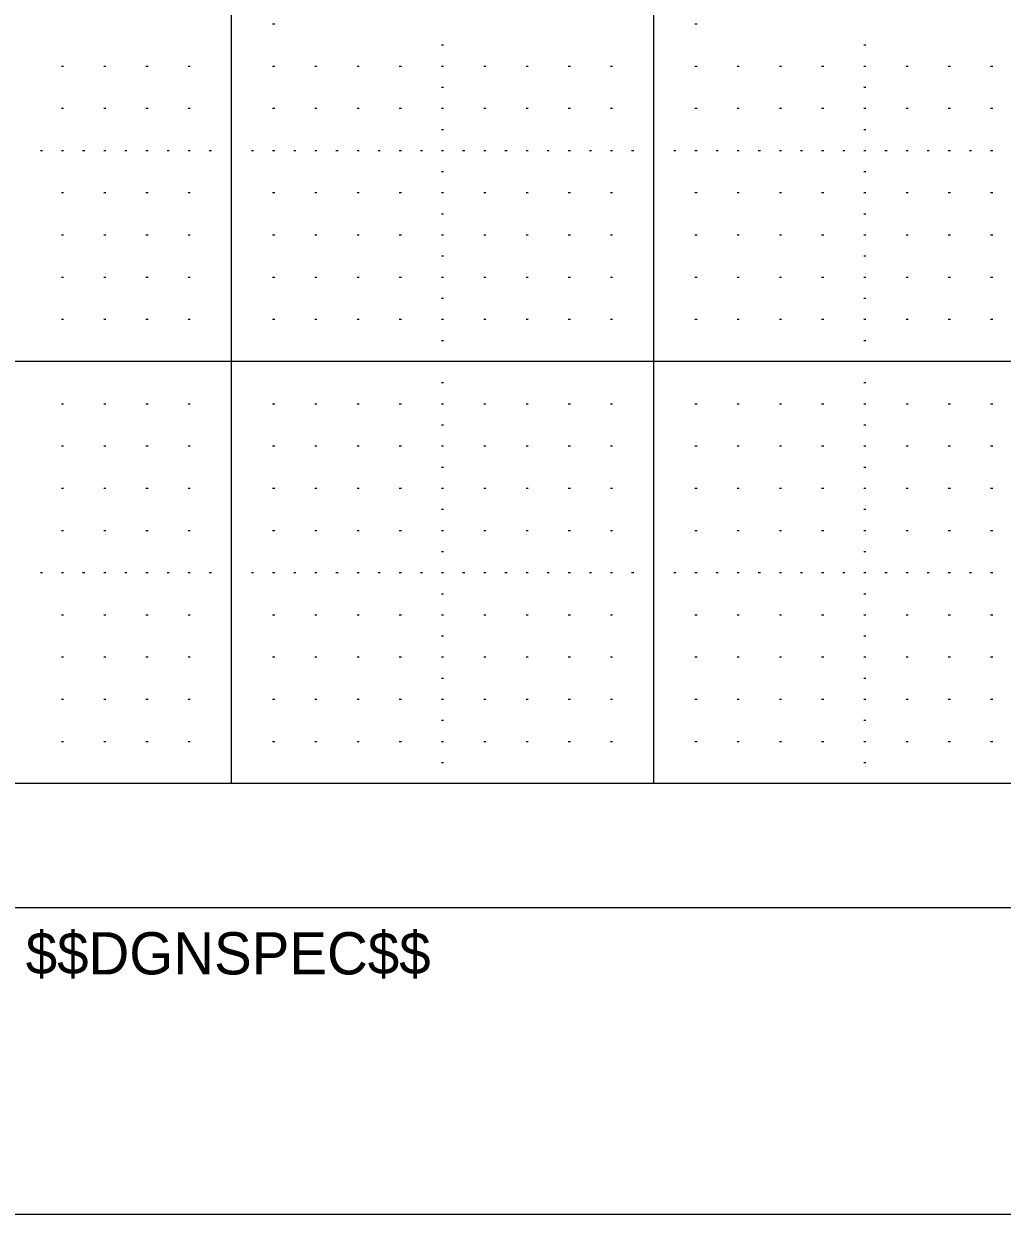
# Model space of a CAD drawing. Extents: x -1.3 to 32.7, y -0.7 to 21.3.
# Drawn here: x 19.601 to 21.917, y -0.727 to 2.093 of the extents above; entities that cross this region are included whole.
import ezdxf

# ---------------------------------------------------------------- set-up
doc = ezdxf.new("R2010")
doc.units = 0
for name, color, linetype in [('Level 1', 7, 'Continuous'), ('Level 4', 7, 'Continuous'), ('Level 48', 7, 'Continuous'), ('Level 5', 7, 'Continuous'), ('Level 63', 7, 'Continuous'), ('R_Border_Dark', 7, 'Continuous')]:
    doc.layers.add(name, color=color, linetype=linetype)

msp = doc.modelspace()

# ---------------------------------------------------------------- linework, layer by layer
at = {"layer": 'Level 1'}
msp.add_line((31.9643, -0.001), (0.3463, -0.001), dxfattribs=at)
at = {"layer": 'Level 4'}
msp.add_line((31.9643, 0.293), (0.3463, 0.293), dxfattribs=at)
at = {"layer": 'Level 5'}
for p, q in [((20.1898, 2.093), (20.1948, 2.093)), ((21.1898, 2.093), (21.1948, 2.093)), ((20.5898, 2.043), (20.5948, 2.043)), ((21.5898, 2.043), (21.5948, 2.043)), ((19.6898, 1.993), (19.6948, 1.993)), ((19.7898, 1.993), (19.7948, 1.993)), ((19.8898, 1.993), (19.8948, 1.993)), ((19.9898, 1.993), (19.9948, 1.993)), ((20.1898, 1.993), (20.1948, 1.993)), ((20.2898, 1.993), (20.2948, 1.993)), ((20.3898, 1.993), (20.3948, 1.993)), ((20.4898, 1.993), (20.4948, 1.993)), ((20.5898, 1.993), (20.5948, 1.993)), ((20.6898, 1.993), (20.6948, 1.993)), ((20.7898, 1.993), (20.7948, 1.993)), ((20.8898, 1.993), (20.8948, 1.993)), ((20.9898, 1.993), (20.9948, 1.993)), ((21.1898, 1.993), (21.1948, 1.993)), ((21.2898, 1.993), (21.2948, 1.993)), ((21.3898, 1.993), (21.3948, 1.993)), ((21.4898, 1.993), (21.4948, 1.993)), ((21.5898, 1.993), (21.5948, 1.993)), ((21.6898, 1.993), (21.6948, 1.993)), ((21.7898, 1.993), (21.7948, 1.993)), ((21.8898, 1.993), (21.8948, 1.993)), ((20.5898, 1.943), (20.5948, 1.943)), ((21.5898, 1.943), (21.5948, 1.943)), ((19.6898, 1.893), (19.6948, 1.893)), ((19.7898, 1.893), (19.7948, 1.893)), ((19.8898, 1.893), (19.8948, 1.893)), ((19.9898, 1.893), (19.9948, 1.893)), ((20.1898, 1.893), (20.1948, 1.893)), ((20.2898, 1.893), (20.2948, 1.893)), ((20.3898, 1.893), (20.3948, 1.893)), ((20.4898, 1.893), (20.4948, 1.893)), ((20.5898, 1.893), (20.5948, 1.893)), ((20.6898, 1.893), (20.6948, 1.893)), ((20.7898, 1.893), (20.7948, 1.893)), ((20.8898, 1.893), (20.8948, 1.893)), ((20.9898, 1.893), (20.9948, 1.893)), ((21.1898, 1.893), (21.1948, 1.893)), ((21.2898, 1.893), (21.2948, 1.893)), ((21.3898, 1.893), (21.3948, 1.893)), ((21.4898, 1.893), (21.4948, 1.893)), ((21.5898, 1.893), (21.5948, 1.893)), ((21.6898, 1.893), (21.6948, 1.893)), ((21.7898, 1.893), (21.7948, 1.893)), ((21.8898, 1.893), (21.8948, 1.893)), ((20.5898, 1.843), (20.5948, 1.843)), ((21.5898, 1.843), (21.5948, 1.843)), ((19.6398, 1.793), (19.6448, 1.793)), ((19.6898, 1.793), (19.6948, 1.793)), ((19.7398, 1.793), (19.7448, 1.793)), ((19.7898, 1.793), (19.7948, 1.793)), ((19.8398, 1.793), (19.8448, 1.793)), ((19.8898, 1.793), (19.8948, 1.793)), ((19.9398, 1.793), (19.9448, 1.793)), ((19.9898, 1.793), (19.9948, 1.793)), ((20.0398, 1.793), (20.0448, 1.793)), ((20.1398, 1.793), (20.1448, 1.793)), ((20.1898, 1.793), (20.1948, 1.793)), ((20.2398, 1.793), (20.2448, 1.793)), ((20.2898, 1.793), (20.2948, 1.793)), ((20.3398, 1.793), (20.3448, 1.793)), ((20.3898, 1.793), (20.3948, 1.793)), ((20.4398, 1.793), (20.4448, 1.793)), ((20.4898, 1.793), (20.4948, 1.793)), ((20.5398, 1.793), (20.5448, 1.793)), ((20.5898, 1.793), (20.5948, 1.793)), ((20.6398, 1.793), (20.6448, 1.793)), ((20.6898, 1.793), (20.6948, 1.793)), ((20.7398, 1.793), (20.7448, 1.793)), ((20.7898, 1.793), (20.7948, 1.793)), ((20.8398, 1.793), (20.8448, 1.793)), ((20.8898, 1.793), (20.8948, 1.793)), ((20.9398, 1.793), (20.9448, 1.793)), ((20.9898, 1.793), (20.9948, 1.793)), ((21.0398, 1.793), (21.0448, 1.793)), ((21.1398, 1.793), (21.1448, 1.793)), ((21.1898, 1.793), (21.1948, 1.793)), ((21.2398, 1.793), (21.2448, 1.793)), ((21.2898, 1.793), (21.2948, 1.793)), ((21.3398, 1.793), (21.3448, 1.793)), ((21.3898, 1.793), (21.3948, 1.793)), ((21.4398, 1.793), (21.4448, 1.793)), ((21.4898, 1.793), (21.4948, 1.793)), ((21.5398, 1.793), (21.5448, 1.793)), ((21.5898, 1.793), (21.5948, 1.793)), ((21.6398, 1.793), (21.6448, 1.793)), ((21.6898, 1.793), (21.6948, 1.793)), ((21.7398, 1.793), (21.7448, 1.793)), ((21.7898, 1.793), (21.7948, 1.793)), ((21.8398, 1.793), (21.8448, 1.793)), ((21.8898, 1.793), (21.8948, 1.793)), ((20.5898, 1.743), (20.5948, 1.743)), ((21.5898, 1.743), (21.5948, 1.743)), ((19.6898, 1.693), (19.6948, 1.693)), ((19.7898, 1.693), (19.7948, 1.693)), ((19.8898, 1.693), (19.8948, 1.693)), ((19.9898, 1.693), (19.9948, 1.693)), ((20.1898, 1.693), (20.1948, 1.693)), ((20.2898, 1.693), (20.2948, 1.693)), ((20.3898, 1.693), (20.3948, 1.693)), ((20.4898, 1.693), (20.4948, 1.693)), ((20.5898, 1.693), (20.5948, 1.693)), ((20.6898, 1.693), (20.6948, 1.693)), ((20.7898, 1.693), (20.7948, 1.693)), ((20.8898, 1.693), (20.8948, 1.693)), ((20.9898, 1.693), (20.9948, 1.693)), ((21.1898, 1.693), (21.1948, 1.693)), ((21.2898, 1.693), (21.2948, 1.693)), ((21.3898, 1.693), (21.3948, 1.693)), ((21.4898, 1.693), (21.4948, 1.693)), ((21.5898, 1.693), (21.5948, 1.693)), ((21.6898, 1.693), (21.6948, 1.693)), ((21.7898, 1.693), (21.7948, 1.693)), ((21.8898, 1.693), (21.8948, 1.693)), ((20.5898, 1.643), (20.5948, 1.643)), ((21.5898, 1.643), (21.5948, 1.643)), ((19.6898, 1.593), (19.6948, 1.593)), ((19.7898, 1.593), (19.7948, 1.593)), ((19.8898, 1.593), (19.8948, 1.593)), ((19.9898, 1.593), (19.9948, 1.593)), ((20.1898, 1.593), (20.1948, 1.593)), ((20.2898, 1.593), (20.2948, 1.593)), ((20.3898, 1.593), (20.3948, 1.593)), ((20.4898, 1.593), (20.4948, 1.593)), ((20.5898, 1.593), (20.5948, 1.593)), ((20.6898, 1.593), (20.6948, 1.593)), ((20.7898, 1.593), (20.7948, 1.593)), ((20.8898, 1.593), (20.8948, 1.593)), ((20.9898, 1.593), (20.9948, 1.593)), ((21.1898, 1.593), (21.1948, 1.593)), ((21.2898, 1.593), (21.2948, 1.593)), ((21.3898, 1.593), (21.3948, 1.593)), ((21.4898, 1.593), (21.4948, 1.593)), ((21.5898, 1.593), (21.5948, 1.593)), ((21.6898, 1.593), (21.6948, 1.593)), ((21.7898, 1.593), (21.7948, 1.593)), ((21.8898, 1.593), (21.8948, 1.593)), ((20.5898, 1.543), (20.5948, 1.543)), ((21.5898, 1.543), (21.5948, 1.543)), ((19.6898, 1.493), (19.6948, 1.493)), ((19.7898, 1.493), (19.7948, 1.493)), ((19.8898, 1.493), (19.8948, 1.493)), ((19.9898, 1.493), (19.9948, 1.493)), ((20.1898, 1.493), (20.1948, 1.493)), ((20.2898, 1.493), (20.2948, 1.493)), ((20.3898, 1.493), (20.3948, 1.493)), ((20.4898, 1.493), (20.4948, 1.493)), ((20.5898, 1.493), (20.5948, 1.493)), ((20.6898, 1.493), (20.6948, 1.493)), ((20.7898, 1.493), (20.7948, 1.493)), ((20.8898, 1.493), (20.8948, 1.493)), ((20.9898, 1.493), (20.9948, 1.493)), ((21.1898, 1.493), (21.1948, 1.493)), ((21.2898, 1.493), (21.2948, 1.493)), ((21.3898, 1.493), (21.3948, 1.493)), ((21.4898, 1.493), (21.4948, 1.493)), ((21.5898, 1.493), (21.5948, 1.493)), ((21.6898, 1.493), (21.6948, 1.493)), ((21.7898, 1.493), (21.7948, 1.493)), ((21.8898, 1.493), (21.8948, 1.493)), ((20.5898, 1.443), (20.5948, 1.443)), ((21.5898, 1.443), (21.5948, 1.443)), ((19.6898, 1.393), (19.6948, 1.393)), ((19.7898, 1.393), (19.7948, 1.393)), ((19.8898, 1.393), (19.8948, 1.393)), ((19.9898, 1.393), (19.9948, 1.393)), ((20.1898, 1.393), (20.1948, 1.393)), ((20.2898, 1.393), (20.2948, 1.393)), ((20.3898, 1.393), (20.3948, 1.393)), ((20.4898, 1.393), (20.4948, 1.393)), ((20.5898, 1.393), (20.5948, 1.393)), ((20.6898, 1.393), (20.6948, 1.393)), ((20.7898, 1.393), (20.7948, 1.393)), ((20.8898, 1.393), (20.8948, 1.393)), ((20.9898, 1.393), (20.9948, 1.393)), ((21.1898, 1.393), (21.1948, 1.393)), ((21.2898, 1.393), (21.2948, 1.393)), ((21.3898, 1.393), (21.3948, 1.393)), ((21.4898, 1.393), (21.4948, 1.393)), ((21.5898, 1.393), (21.5948, 1.393)), ((21.6898, 1.393), (21.6948, 1.393)), ((21.7898, 1.393), (21.7948, 1.393)), ((21.8898, 1.393), (21.8948, 1.393)), ((20.5898, 1.343), (20.5948, 1.343)), ((21.5898, 1.343), (21.5948, 1.343)), ((20.5898, 1.243), (20.5948, 1.243)), ((21.5898, 1.243), (21.5948, 1.243)), ((19.6898, 1.193), (19.6948, 1.193)), ((19.7898, 1.193), (19.7948, 1.193)), ((19.8898, 1.193), (19.8948, 1.193)), ((19.9898, 1.193), (19.9948, 1.193)), ((20.1898, 1.193), (20.1948, 1.193)), ((20.2898, 1.193), (20.2948, 1.193)), ((20.3898, 1.193), (20.3948, 1.193)), ((20.4898, 1.193), (20.4948, 1.193)), ((20.5898, 1.193), (20.5948, 1.193)), ((20.6898, 1.193), (20.6948, 1.193)), ((20.7898, 1.193), (20.7948, 1.193)), ((20.8898, 1.193), (20.8948, 1.193)), ((20.9898, 1.193), (20.9948, 1.193)), ((21.1898, 1.193), (21.1948, 1.193)), ((21.2898, 1.193), (21.2948, 1.193)), ((21.3898, 1.193), (21.3948, 1.193)), ((21.4898, 1.193), (21.4948, 1.193)), ((21.5898, 1.193), (21.5948, 1.193)), ((21.6898, 1.193), (21.6948, 1.193)), ((21.7898, 1.193), (21.7948, 1.193)), ((21.8898, 1.193), (21.8948, 1.193)), ((20.5898, 1.143), (20.5948, 1.143)), ((21.5898, 1.143), (21.5948, 1.143)), ((19.6898, 1.093), (19.6948, 1.093)), ((19.7898, 1.093), (19.7948, 1.093)), ((19.8898, 1.093), (19.8948, 1.093)), ((19.9898, 1.093), (19.9948, 1.093)), ((20.1898, 1.093), (20.1948, 1.093)), ((20.2898, 1.093), (20.2948, 1.093)), ((20.3898, 1.093), (20.3948, 1.093)), ((20.4898, 1.093), (20.4948, 1.093)), ((20.5898, 1.093), (20.5948, 1.093)), ((20.6898, 1.093), (20.6948, 1.093)), ((20.7898, 1.093), (20.7948, 1.093)), ((20.8898, 1.093), (20.8948, 1.093)), ((20.9898, 1.093), (20.9948, 1.093)), ((21.1898, 1.093), (21.1948, 1.093)), ((21.2898, 1.093), (21.2948, 1.093)), ((21.3898, 1.093), (21.3948, 1.093)), ((21.4898, 1.093), (21.4948, 1.093)), ((21.5898, 1.093), (21.5948, 1.093)), ((21.6898, 1.093), (21.6948, 1.093)), ((21.7898, 1.093), (21.7948, 1.093)), ((21.8898, 1.093), (21.8948, 1.093)), ((20.5898, 1.043), (20.5948, 1.043)), ((21.5898, 1.043), (21.5948, 1.043)), ((19.6898, 0.993), (19.6948, 0.993)), ((19.7898, 0.993), (19.7948, 0.993)), ((19.8898, 0.993), (19.8948, 0.993)), ((19.9898, 0.993), (19.9948, 0.993)), ((20.1898, 0.993), (20.1948, 0.993)), ((20.2898, 0.993), (20.2948, 0.993)), ((20.3898, 0.993), (20.3948, 0.993)), ((20.4898, 0.993), (20.4948, 0.993)), ((20.5898, 0.993), (20.5948, 0.993)), ((20.6898, 0.993), (20.6948, 0.993)), ((20.7898, 0.993), (20.7948, 0.993)), ((20.8898, 0.993), (20.8948, 0.993)), ((20.9898, 0.993), (20.9948, 0.993)), ((21.1898, 0.993), (21.1948, 0.993)), ((21.2898, 0.993), (21.2948, 0.993)), ((21.3898, 0.993), (21.3948, 0.993)), ((21.4898, 0.993), (21.4948, 0.993)), ((21.5898, 0.993), (21.5948, 0.993)), ((21.6898, 0.993), (21.6948, 0.993)), ((21.7898, 0.993), (21.7948, 0.993)), ((21.8898, 0.993), (21.8948, 0.993)), ((20.5898, 0.943), (20.5948, 0.943)), ((21.5898, 0.943), (21.5948, 0.943)), ((19.6898, 0.893), (19.6948, 0.893)), ((19.7898, 0.893), (19.7948, 0.893)), ((19.8898, 0.893), (19.8948, 0.893)), ((19.9898, 0.893), (19.9948, 0.893)), ((20.1898, 0.893), (20.1948, 0.893)), ((20.2898, 0.893), (20.2948, 0.893)), ((20.3898, 0.893), (20.3948, 0.893)), ((20.4898, 0.893), (20.4948, 0.893)), ((20.5898, 0.893), (20.5948, 0.893)), ((20.6898, 0.893), (20.6948, 0.893)), ((20.7898, 0.893), (20.7948, 0.893)), ((20.8898, 0.893), (20.8948, 0.893)), ((20.9898, 0.893), (20.9948, 0.893)), ((21.1898, 0.893), (21.1948, 0.893)), ((21.2898, 0.893), (21.2948, 0.893)), ((21.3898, 0.893), (21.3948, 0.893)), ((21.4898, 0.893), (21.4948, 0.893)), ((21.5898, 0.893), (21.5948, 0.893)), ((21.6898, 0.893), (21.6948, 0.893)), ((21.7898, 0.893), (21.7948, 0.893)), ((21.8898, 0.893), (21.8948, 0.893)), ((20.5898, 0.843), (20.5948, 0.843)), ((21.5898, 0.843), (21.5948, 0.843)), ((19.6398, 0.793), (19.6448, 0.793)), ((19.6898, 0.793), (19.6948, 0.793)), ((19.7398, 0.793), (19.7448, 0.793)), ((19.7898, 0.793), (19.7948, 0.793)), ((19.8398, 0.793), (19.8448, 0.793)), ((19.8898, 0.793), (19.8948, 0.793)), ((19.9398, 0.793), (19.9448, 0.793)), ((19.9898, 0.793), (19.9948, 0.793)), ((20.0398, 0.793), (20.0448, 0.793)), ((20.1398, 0.793), (20.1448, 0.793)), ((20.1898, 0.793), (20.1948, 0.793)), ((20.2398, 0.793), (20.2448, 0.793)), ((20.2898, 0.793), (20.2948, 0.793)), ((20.3398, 0.793), (20.3448, 0.793)), ((20.3898, 0.793), (20.3948, 0.793)), ((20.4398, 0.793), (20.4448, 0.793)), ((20.4898, 0.793), (20.4948, 0.793)), ((20.5398, 0.793), (20.5448, 0.793)), ((20.5898, 0.793), (20.5948, 0.793)), ((20.6398, 0.793), (20.6448, 0.793)), ((20.6898, 0.793), (20.6948, 0.793)), ((20.7398, 0.793), (20.7448, 0.793)), ((20.7898, 0.793), (20.7948, 0.793)), ((20.8398, 0.793), (20.8448, 0.793)), ((20.8898, 0.793), (20.8948, 0.793)), ((20.9398, 0.793), (20.9448, 0.793)), ((20.9898, 0.793), (20.9948, 0.793)), ((21.0398, 0.793), (21.0448, 0.793)), ((21.1398, 0.793), (21.1448, 0.793)), ((21.1898, 0.793), (21.1948, 0.793)), ((21.2398, 0.793), (21.2448, 0.793)), ((21.2898, 0.793), (21.2948, 0.793)), ((21.3398, 0.793), (21.3448, 0.793)), ((21.3898, 0.793), (21.3948, 0.793)), ((21.4398, 0.793), (21.4448, 0.793)), ((21.4898, 0.793), (21.4948, 0.793)), ((21.5398, 0.793), (21.5448, 0.793)), ((21.5898, 0.793), (21.5948, 0.793)), ((21.6398, 0.793), (21.6448, 0.793)), ((21.6898, 0.793), (21.6948, 0.793)), ((21.7398, 0.793), (21.7448, 0.793)), ((21.7898, 0.793), (21.7948, 0.793)), ((21.8398, 0.793), (21.8448, 0.793)), ((21.8898, 0.793), (21.8948, 0.793)), ((20.5898, 0.743), (20.5948, 0.743)), ((21.5898, 0.743), (21.5948, 0.743)), ((19.6898, 0.693), (19.6948, 0.693)), ((19.7898, 0.693), (19.7948, 0.693)), ((19.8898, 0.693), (19.8948, 0.693)), ((19.9898, 0.693), (19.9948, 0.693)), ((20.1898, 0.693), (20.1948, 0.693)), ((20.2898, 0.693), (20.2948, 0.693)), ((20.3898, 0.693), (20.3948, 0.693)), ((20.4898, 0.693), (20.4948, 0.693)), ((20.5898, 0.693), (20.5948, 0.693)), ((20.6898, 0.693), (20.6948, 0.693)), ((20.7898, 0.693), (20.7948, 0.693)), ((20.8898, 0.693), (20.8948, 0.693)), ((20.9898, 0.693), (20.9948, 0.693)), ((21.1898, 0.693), (21.1948, 0.693)), ((21.2898, 0.693), (21.2948, 0.693)), ((21.3898, 0.693), (21.3948, 0.693)), ((21.4898, 0.693), (21.4948, 0.693)), ((21.5898, 0.693), (21.5948, 0.693)), ((21.6898, 0.693), (21.6948, 0.693)), ((21.7898, 0.693), (21.7948, 0.693)), ((21.8898, 0.693), (21.8948, 0.693)), ((20.5898, 0.643), (20.5948, 0.643)), ((21.5898, 0.643), (21.5948, 0.643)), ((19.6898, 0.593), (19.6948, 0.593)), ((19.7898, 0.593), (19.7948, 0.593)), ((19.8898, 0.593), (19.8948, 0.593)), ((19.9898, 0.593), (19.9948, 0.593)), ((20.1898, 0.593), (20.1948, 0.593)), ((20.2898, 0.593), (20.2948, 0.593)), ((20.3898, 0.593), (20.3948, 0.593)), ((20.4898, 0.593), (20.4948, 0.593)), ((20.5898, 0.593), (20.5948, 0.593)), ((20.6898, 0.593), (20.6948, 0.593)), ((20.7898, 0.593), (20.7948, 0.593)), ((20.8898, 0.593), (20.8948, 0.593)), ((20.9898, 0.593), (20.9948, 0.593)), ((21.1898, 0.593), (21.1948, 0.593)), ((21.2898, 0.593), (21.2948, 0.593)), ((21.3898, 0.593), (21.3948, 0.593)), ((21.4898, 0.593), (21.4948, 0.593)), ((21.5898, 0.593), (21.5948, 0.593)), ((21.6898, 0.593), (21.6948, 0.593)), ((21.7898, 0.593), (21.7948, 0.593)), ((21.8898, 0.593), (21.8948, 0.593)), ((20.5898, 0.543), (20.5948, 0.543)), ((21.5898, 0.543), (21.5948, 0.543)), ((19.6898, 0.493), (19.6948, 0.493)), ((19.7898, 0.493), (19.7948, 0.493)), ((19.8898, 0.493), (19.8948, 0.493)), ((19.9898, 0.493), (19.9948, 0.493)), ((20.1898, 0.493), (20.1948, 0.493)), ((20.2898, 0.493), (20.2948, 0.493)), ((20.3898, 0.493), (20.3948, 0.493)), ((20.4898, 0.493), (20.4948, 0.493)), ((20.5898, 0.493), (20.5948, 0.493)), ((20.6898, 0.493), (20.6948, 0.493)), ((20.7898, 0.493), (20.7948, 0.493)), ((20.8898, 0.493), (20.8948, 0.493)), ((20.9898, 0.493), (20.9948, 0.493)), ((21.1898, 0.493), (21.1948, 0.493)), ((21.2898, 0.493), (21.2948, 0.493)), ((21.3898, 0.493), (21.3948, 0.493)), ((21.4898, 0.493), (21.4948, 0.493)), ((21.5898, 0.493), (21.5948, 0.493)), ((21.6898, 0.493), (21.6948, 0.493)), ((21.7898, 0.493), (21.7948, 0.493)), ((21.8898, 0.493), (21.8948, 0.493)), ((20.5898, 0.443), (20.5948, 0.443)), ((21.5898, 0.443), (21.5948, 0.443)), ((19.6898, 0.393), (19.6948, 0.393)), ((19.7898, 0.393), (19.7948, 0.393)), ((19.8898, 0.393), (19.8948, 0.393)), ((19.9898, 0.393), (19.9948, 0.393)), ((20.1898, 0.393), (20.1948, 0.393)), ((20.2898, 0.393), (20.2948, 0.393)), ((20.3898, 0.393), (20.3948, 0.393)), ((20.4898, 0.393), (20.4948, 0.393)), ((20.5898, 0.393), (20.5948, 0.393)), ((20.6898, 0.393), (20.6948, 0.393)), ((20.7898, 0.393), (20.7948, 0.393)), ((20.8898, 0.393), (20.8948, 0.393)), ((20.9898, 0.393), (20.9948, 0.393)), ((21.1898, 0.393), (21.1948, 0.393)), ((21.2898, 0.393), (21.2948, 0.393)), ((21.3898, 0.393), (21.3948, 0.393)), ((21.4898, 0.393), (21.4948, 0.393)), ((21.5898, 0.393), (21.5948, 0.393)), ((21.6898, 0.393), (21.6948, 0.393)), ((21.7898, 0.393), (21.7948, 0.393)), ((21.8898, 0.393), (21.8948, 0.393)), ((20.5898, 0.343), (20.5948, 0.343)), ((21.5898, 0.343), (21.5948, 0.343))]:
    msp.add_line(p, q, dxfattribs=at)
at = {"layer": 'Level 63'}
msp.add_lwpolyline([(-1.263, -0.727), (32.737, -0.727), (32.737, 21.273), (-1.263, 21.273)], close=True, dxfattribs=at)
msp.add_lwpolyline([(31.0923, 10.293), (31.0923, 0.293), (1.0923, 0.293), (1.0923, 8.293)], dxfattribs=at)
at = {"layer": 'R_Border_Dark'}
for p, q in [((20.0923, 0.293), (20.0923, 10.293)), ((21.0923, 0.293), (21.0923, 10.293)), ((31.9643, 1.293), (0.3463, 1.293))]:
    msp.add_line(p, q, dxfattribs=at)
msp.add_lwpolyline([(31.0923, 10.293), (31.0923, 0.293), (1.0923, 0.293), (1.0923, 8.293)], dxfattribs=at)

# ---------------------------------------------------------------- texts
at = {"layer": 'Level 48'}
msp.add_text('$$DGNSPEC$$', height=0.100002, dxfattribs=at).set_placement((19.6051, -0.159))

doc.saveas('drawing.dxf')
